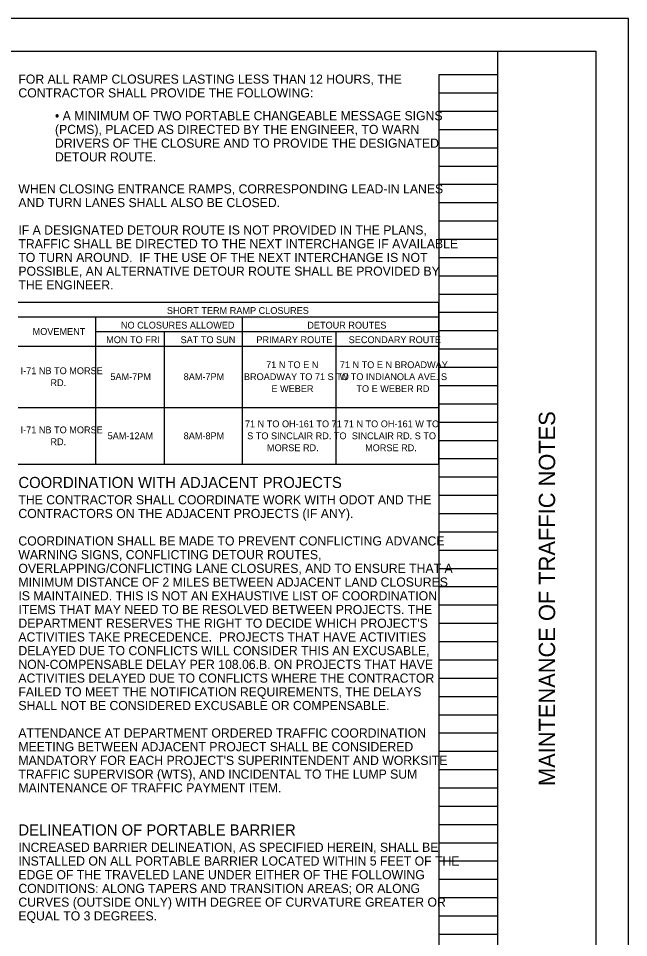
# Model space of a CAD drawing. Extents: x 0 to 34, y 0 to 22.
# Drawn here: x 24.66 to 34, y 7.93 to 22 of the extents above; entities that cross this region are included whole.
import ezdxf

# ---------------------------------------------------------------- set-up
doc = ezdxf.new("R2010")
doc.units = 0
for name, color, linetype in [('SH_Border', 7, 'Continuous'), ('SH_Cut_Line', 7, 'Continuous'), ('SH_Data', 7, 'Continuous'), ('SH_Text', 7, 'Continuous')]:
    doc.layers.add(name, color=color, linetype=linetype)

msp = doc.modelspace()

# ---------------------------------------------------------------- linework, layer by layer
at = {"layer": 'SH_Border'}
msp.add_line((32, 0.5), (32, 21.5), dxfattribs=at)
msp.add_lwpolyline([(1.5, 21.5), (33.5, 21.5), (33.5, 0.5), (1.5, 0.5)], close=True, dxfattribs=at)
at = {"layer": 'SH_Cut_Line'}
msp.add_lwpolyline([(0, 0), (34, 0), (34, 22), (0, 22)], close=True, dxfattribs=at)
at = {"layer": 'SH_Data'}
for p, q in [((31.1, 0.98), (31.1, 21.14)), ((31.1, 21.14), (32, 21.14)), ((32, 0.98), (32, 21.14)), ((31.1, 20.86), (32, 20.86)), ((31.1, 20.58), (32, 20.58)), ((31.1, 20.3), (32, 20.3)), ((31.1, 20.02), (32, 20.02)), ((31.1, 19.74), (32, 19.74)), ((31.1, 19.46), (32, 19.46)), ((31.1, 19.18), (32, 19.18)), ((31.1, 18.9), (32, 18.9)), ((31.1, 18.62), (32, 18.62)), ((31.1, 18.34), (32, 18.34)), ((31.1, 18.06), (32, 18.06)), ((31.1, 17.78), (32, 17.78)), ((24.658, 17.653), (31.092, 17.653)), ((31.092, 17.653), (31.092, 15.174)), ((31.1, 17.5), (32, 17.5)), ((24.658, 17.43), (31.092, 17.43)), ((25.842, 17.43), (25.842, 15.174)), ((28.087, 17.43), (28.087, 15.174)), ((25.842, 17.207), (31.092, 17.207)), ((26.892, 17.207), (26.892, 15.174)), ((29.517, 17.207), (29.517, 15.174)), ((31.1, 17.22), (32, 17.22)), ((24.658, 16.983), (31.092, 16.983)), ((31.1, 16.94), (32, 16.94)), ((31.1, 16.66), (32, 16.66)), ((31.1, 16.38), (32, 16.38)), ((24.658, 16.045), (31.092, 16.045)), ((31.1, 16.1), (32, 16.1)), ((31.1, 15.82), (32, 15.82)), ((31.1, 15.54), (32, 15.54)), ((31.1, 15.26), (32, 15.26)), ((24.658, 15.174), (31.092, 15.174)), ((31.1, 14.98), (32, 14.98)), ((31.1, 14.7), (32, 14.7)), ((31.1, 14.42), (32, 14.42)), ((31.1, 14.14), (32, 14.14)), ((31.1, 13.86), (32, 13.86)), ((31.1, 13.58), (32, 13.58)), ((31.1, 13.3), (32, 13.3)), ((31.1, 13.02), (32, 13.02)), ((31.1, 12.74), (32, 12.74)), ((31.1, 12.46), (32, 12.46)), ((31.1, 12.18), (32, 12.18)), ((31.1, 11.9), (32, 11.9)), ((31.1, 11.62), (32, 11.62)), ((31.1, 11.34), (32, 11.34)), ((31.1, 11.06), (32, 11.06)), ((31.1, 10.78), (32, 10.78)), ((31.1, 10.5), (32, 10.5)), ((31.1, 10.22), (32, 10.22)), ((31.1, 9.94), (32, 9.94)), ((31.1, 9.66), (32, 9.66)), ((31.1, 9.38), (32, 9.38)), ((31.1, 9.1), (32, 9.1)), ((31.1, 8.82), (32, 8.82)), ((31.1, 8.54), (32, 8.54)), ((31.1, 8.26), (32, 8.26)), ((31.1, 7.98), (32, 7.98))]:
    msp.add_line(p, q, dxfattribs=at)

# ---------------------------------------------------------------- texts
msp.add_text('MAINTENANCE OF TRAFFIC NOTES', height=0.25, rotation=90, dxfattribs=at).set_placement((32.875, 10.247))
at = {"layer": 'SH_Text'}
for s, height, p in [('FOR ALL RAMP CLOSURES LASTING LESS THAN 12 HOURS, THE ', 0.14, (24.66, 21)), ('CONTRACTOR SHALL PROVIDE THE FOLLOWING:', 0.14, (24.66, 20.79)), ('• A MINIMUM OF TWO PORTABLE CHANGEABLE MESSAGE SIGNS ', 0.14, (25.22, 20.44)), ('(PCMS), PLACED AS DIRECTED BY THE ENGINEER, TO WARN ', 0.14, (25.22, 20.23)), ('DRIVERS OF THE CLOSURE AND TO PROVIDE THE DESIGNATED ', 0.14, (25.22, 20.02)), ('DETOUR ROUTE.', 0.14, (25.22, 19.81)), ('WHEN CLOSING ENTRANCE RAMPS, CORRESPONDING LEAD-IN LANES ', 0.14, (24.66, 19.32)), ('AND TURN LANES SHALL ALSO BE CLOSED.', 0.14, (24.66, 19.11)), ('IF A DESIGNATED DETOUR ROUTE IS NOT PROVIDED IN THE PLANS, ', 0.14, (24.66, 18.69)), ('TRAFFIC SHALL BE DIRECTED TO THE NEXT INTERCHANGE IF AVAILABLE ', 0.14, (24.66, 18.48)), ('TO TURN AROUND.  IF THE USE OF THE NEXT INTERCHANGE IS NOT ', 0.14, (24.66, 18.27)), ('POSSIBLE, AN ALTERNATIVE DETOUR ROUTE SHALL BE PROVIDED BY ', 0.14, (24.66, 18.06)), ('THE ENGINEER.', 0.14, (24.66, 17.85)), ('SHORT TERM RAMP CLOSURES', 0.10444, (26.933, 17.475)), ('NO CLOSURES ALLOWED', 0.10444, (26.229, 17.251)), ('DETOUR ROUTES', 0.10444, (29.082, 17.251)), ('MOVEMENT', 0.1044, (24.878, 17.154)), ('MON TO FRI', 0.1044, (26.004, 17.028)), ('SAT TO SUN', 0.1044, (27.143, 17.028)), ('PRIMARY ROUTE', 0.10444, (28.303, 17.028)), ('SECONDARY ROUTE', 0.10444, (29.716, 17.028)), ('71 N TO E N ', 0.10444, (28.452, 16.645)), ('71 N TO E N BROADWAY ', 0.10444, (29.58, 16.645)), ('I-71 NB TO MORSE ', 0.10444, (24.694, 16.553)), ('RD.', 0.1044, (25.151, 16.37)), ('5AM-7PM', 0.1044, (26.068, 16.462)), ('8AM-7PM', 0.1044, (27.19, 16.462)), ('BROADWAY TO 71 S TO ', 0.10444, (28.112, 16.462)), ('W TO INDIANOLA AVE. S ', 0.10444, (29.577, 16.462)), ('E WEBER', 0.1044, (28.533, 16.279)), ('TO E WEBER RD', 0.10444, (29.834, 16.279)), ('71 N TO OH-161 TO 71 ', 0.10444, (28.128, 15.74)), ('71 N TO OH-161 W TO ', 0.10444, (29.64, 15.74)), ('I-71 NB TO MORSE ', 0.10444, (24.694, 15.648)), ('5AM-12AM', 0.1044, (26.026, 15.557)), ('8AM-8PM', 0.1044, (27.19, 15.557)), ('S TO SINCLAIR RD. TO ', 0.10444, (28.162, 15.557)), ('SINCLAIR RD. S TO ', 0.10444, (29.764, 15.557)), ('RD.', 0.1044, (25.151, 15.466)), ('MORSE RD.', 0.1044, (28.465, 15.374)), ('MORSE RD.', 0.1044, (29.967, 15.374)), ('COORDINATION WITH ADJACENT PROJECTS', 0.17, (24.66, 14.81)), ('THE CONTRACTOR SHALL COORDINATE WORK WITH ODOT AND THE ', 0.14, (24.66, 14.56)), ('CONTRACTORS ON THE ADJACENT PROJECTS (IF ANY).', 0.14, (24.66, 14.35)), ('COORDINATION SHALL BE MADE TO PREVENT CONFLICTING ADVANCE ', 0.14, (24.66, 13.93)), ('WARNING SIGNS, CONFLICTING DETOUR ROUTES, ', 0.14, (24.66, 13.72)), ('OVERLAPPING/CONFLICTING LANE CLOSURES, AND TO ENSURE THAT A ', 0.14, (24.66, 13.51)), ('MINIMUM DISTANCE OF 2 MILES BETWEEN ADJACENT LAND CLOSURES ', 0.14, (24.66, 13.3)), ('IS MAINTAINED. THIS IS NOT AN EXHAUSTIVE LIST OF COORDINATION ', 0.14, (24.66, 13.09)), ('ITEMS THAT MAY NEED TO BE RESOLVED BETWEEN PROJECTS. THE ', 0.14, (24.66, 12.88)), ("DEPARTMENT RESERVES THE RIGHT TO DECIDE WHICH PROJECT'S ", 0.14, (24.66, 12.67)), ('ACTIVITIES TAKE PRECEDENCE.  PROJECTS THAT HAVE ACTIVITIES ', 0.14, (24.66, 12.46)), ('DELAYED DUE TO CONFLICTS WILL CONSIDER THIS AN EXCUSABLE, ', 0.14, (24.66, 12.25)), ('NON-COMPENSABLE DELAY PER 108.06.B. ON PROJECTS THAT HAVE ', 0.14, (24.66, 12.04)), ('ACTIVITIES DELAYED DUE TO CONFLICTS WHERE THE CONTRACTOR ', 0.14, (24.66, 11.83)), ('FAILED TO MEET THE NOTIFICATION REQUIREMENTS, THE DELAYS ', 0.14, (24.66, 11.62)), ('SHALL NOT BE CONSIDERED EXCUSABLE OR COMPENSABLE.', 0.14, (24.66, 11.41)), ('ATTENDANCE AT DEPARTMENT ORDERED TRAFFIC COORDINATION ', 0.14, (24.66, 10.99)), ('MEETING BETWEEN ADJACENT PROJECT SHALL BE CONSIDERED ', 0.14, (24.66, 10.78)), ("MANDATORY FOR EACH PROJECT'S SUPERINTENDENT AND WORKSITE ", 0.14, (24.66, 10.57)), ('TRAFFIC SUPERVISOR (WTS), AND INCIDENTAL TO THE LUMP SUM ', 0.14, (24.66, 10.36)), ('MAINTENANCE OF TRAFFIC PAYMENT ITEM.', 0.14, (24.66, 10.15)), ('DELINEATION OF PORTABLE BARRIER', 0.17, (24.66, 9.49)), ('INCREASED BARRIER DELINEATION, AS SPECIFIED HEREIN, SHALL BE ', 0.14, (24.66, 9.24)), ('INSTALLED ON ALL PORTABLE BARRIER LOCATED WITHIN 5 FEET OF THE ', 0.14, (24.66, 9.03)), ('EDGE OF THE TRAVELED LANE UNDER EITHER OF THE FOLLOWING ', 0.14, (24.66, 8.82)), ('CONDITIONS: ALONG TAPERS AND TRANSITION AREAS; OR ALONG ', 0.14, (24.66, 8.61)), ('CURVES (OUTSIDE ONLY) WITH DEGREE OF CURVATURE GREATER OR ', 0.14, (24.66, 8.4)), ('EQUAL TO 3 DEGREES.', 0.14, (24.66, 8.19))]:
    msp.add_text(s, height=height, dxfattribs=at).set_placement(p)

doc.saveas('drawing.dxf')
